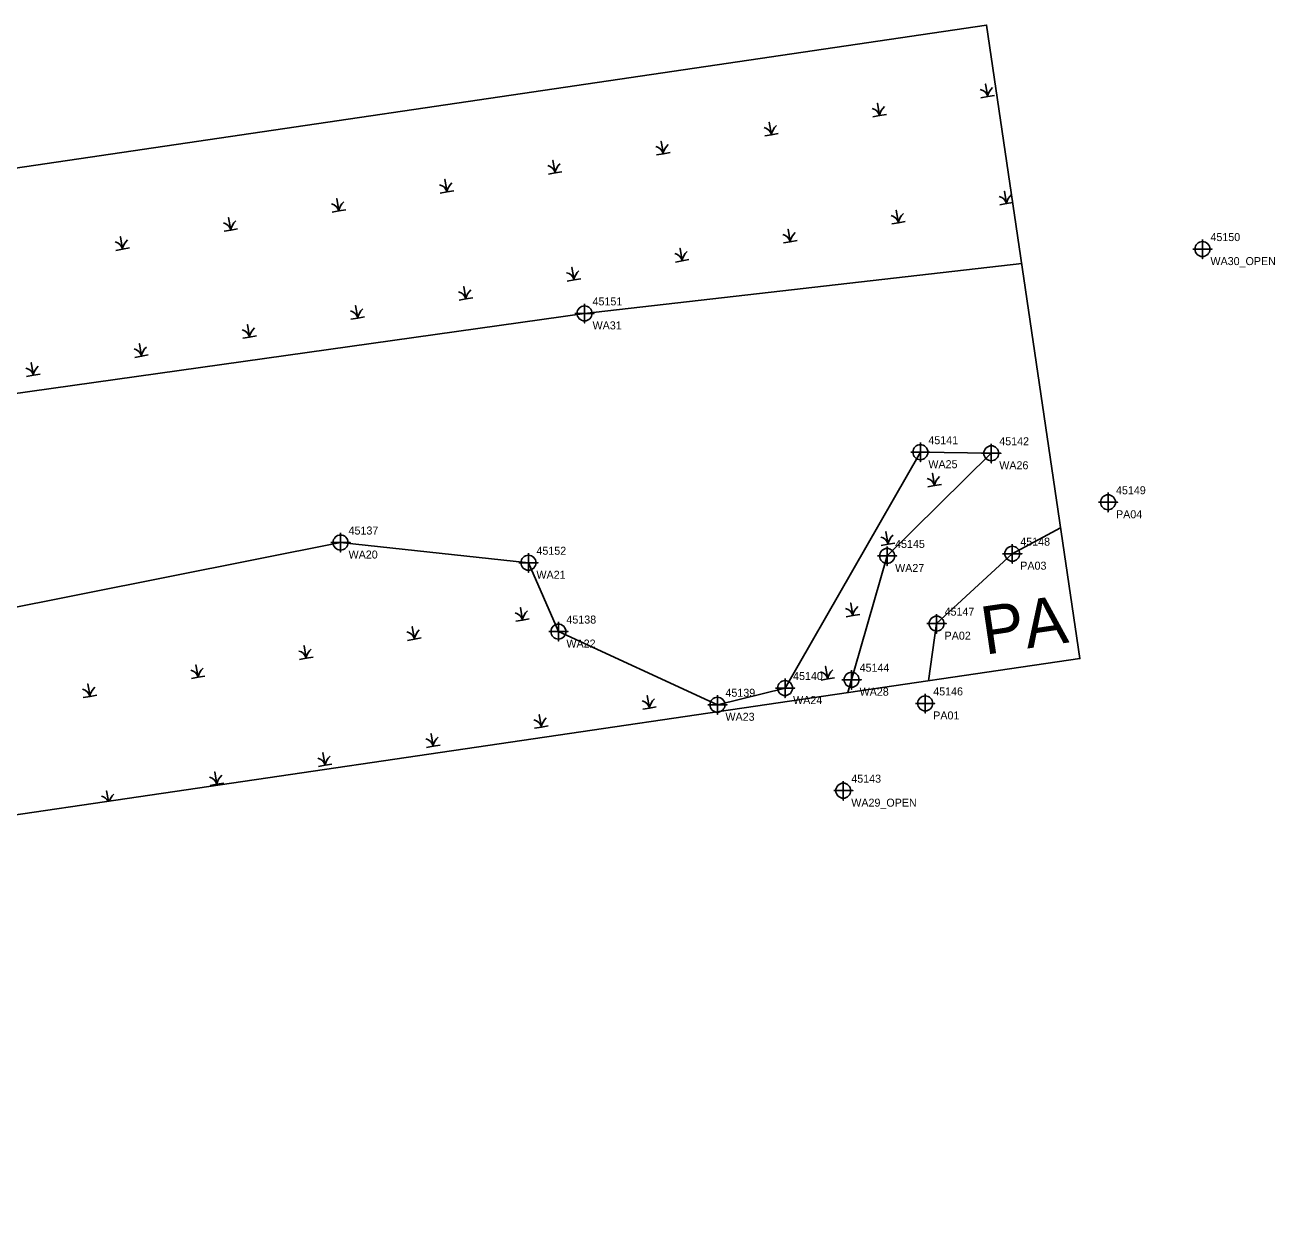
# Model space of a CAD drawing. Extents: x 2111078 to 2112659, y 581517 to 581899.
# Drawn here: x 2112268.6 to 2112659.1, y 581523.2 to 581899.2 of the extents above; entities that cross this region are included whole.
import ezdxf

# ---------------------------------------------------------------- set-up
doc = ezdxf.new("R2010")
doc.units = 0
for name, color, linetype in [('Default', 7, 'Continuous'), ('Exist Environmental Wetland Boundary', 7, 'Continuous'), ('Exist Environmental Wetland Boundary Cogo Comment', 7, 'Continuous'), ('Exist Environmental Wetland Boundary Cogo Number', 7, 'Continuous'), ('Exist Environmental Wetland Boundary Cogo Point CELL', 7, 'Continuous'), ('Exist Hydro Jurisdictional Stream or Body of Water Mitigable', 7, 'Continuous'), ('Exist Hydro Jurisdictional Stream or Body of Water Mitigable Cogo Comment', 7, 'Continuous'), ('Exist Hydro Jurisdictional Stream or Body of Water Mitigable Cogo Number', 7, 'Continuous'), ('Exist Hydro Jurisdictional Stream or Body of Water Mitigable Cogo Point CELL', 7, 'Continuous'), ('Exist Hydro Jurisdictional Stream or Body of Water Mitigable Text', 7, 'Continuous'), ('Exist Hydro Swamp or Marsh', 7, 'Continuous')]:
    doc.layers.add(name, color=color, linetype=linetype)

msp = doc.modelspace()

# ---------------------------------------------------------------- linework, layer by layer
at = {"layer": 'Default'}
msp.add_lwpolyline([(2111089.87, 581523.16), (2111077.52, 581722.78), (2111579.66, 581753.48), (2112568.99, 581899.18), (2112598.13, 581701.32), (2111600.4, 581554.74), (2111516.52, 581549.55)], close=True, dxfattribs=at)
at = {"layer": 'Exist Environmental Wetland Boundary'}
msp.add_lwpolyline([(2112579.95, 581824.73), (2112443.39, 581809.13), (2112256.64, 581782.86), (2112109, 581759.83), (2112096.72, 581743.78), (2112106.82, 581715.7), (2112118.04, 581694.33), (2112231.63, 581710.61), (2112367.17, 581737.55), (2112425.86, 581731.24), (2112435.22, 581709.75), (2112484.9, 581686.89), (2112506.03, 581692.11), (2112548.3, 581765.77), (2112570.44, 581765.42), (2112537.9, 581733.37), (2112525.65, 581690.67)], dxfattribs=at)
at = {"layer": 'Exist Environmental Wetland Boundary Cogo Point CELL'}
for points in [[(2112636.41, 581832.2), (2112636.41, 581826.2), (2112636.41, 581829.2), (2112639.41, 581829.2), (2112633.41, 581829.2)], [(2112443.39, 581812.12), (2112443.39, 581806.12), (2112443.39, 581809.12), (2112446.39, 581809.12), (2112440.39, 581809.12)], [(2112548.29, 581768.77), (2112548.29, 581762.77), (2112548.29, 581765.77), (2112551.29, 581765.77), (2112545.29, 581765.77)], [(2112570.44, 581768.42), (2112570.44, 581762.42), (2112570.44, 581765.42), (2112573.44, 581765.42), (2112567.44, 581765.42)], [(2112367.17, 581740.55), (2112367.17, 581734.55), (2112367.17, 581737.55), (2112370.17, 581737.55), (2112364.17, 581737.55)], [(2112537.9, 581736.36), (2112537.9, 581730.36), (2112537.9, 581733.36), (2112540.9, 581733.36), (2112534.9, 581733.36)], [(2112425.86, 581734.24), (2112425.86, 581728.24), (2112425.86, 581731.24), (2112428.86, 581731.24), (2112422.86, 581731.24)], [(2112435.22, 581712.75), (2112435.22, 581706.75), (2112435.22, 581709.75), (2112438.22, 581709.75), (2112432.22, 581709.75)], [(2112526.81, 581697.71), (2112526.81, 581691.71), (2112526.81, 581694.71), (2112529.81, 581694.71), (2112523.81, 581694.71)], [(2112506.03, 581695.11), (2112506.03, 581689.11), (2112506.03, 581692.11), (2112509.03, 581692.11), (2112503.03, 581692.11)], [(2112484.9, 581689.89), (2112484.9, 581683.89), (2112484.9, 581686.89), (2112487.9, 581686.89), (2112481.9, 581686.89)], [(2112524.21, 581663.06), (2112524.21, 581657.06), (2112524.21, 581660.06), (2112527.21, 581660.06), (2112521.21, 581660.06)]]:
    msp.add_lwpolyline(points, dxfattribs=at)
for centre in [(2112636.41, 581829.2), (2112443.39, 581809.12), (2112548.29, 581765.77), (2112570.44, 581765.42), (2112367.17, 581737.55), (2112537.9, 581733.36), (2112425.86, 581731.24), (2112435.22, 581709.75), (2112526.81, 581694.71), (2112506.03, 581692.11), (2112484.9, 581686.89), (2112524.21, 581660.06)]:
    msp.add_circle(centre, 2.34, dxfattribs=at)
at = {"layer": 'Exist Hydro Jurisdictional Stream or Body of Water Mitigable'}
msp.add_lwpolyline([(2112550.82, 581694.37), (2112553.36, 581712.22), (2112577, 581734.07), (2112592.11, 581742.18)], dxfattribs=at)
at = {"layer": 'Exist Hydro Jurisdictional Stream or Body of Water Mitigable Cogo Point CELL'}
for points in [[(2112606.91, 581753.13), (2112606.91, 581747.13), (2112606.91, 581750.13), (2112609.91, 581750.13), (2112603.91, 581750.13)], [(2112577, 581737.07), (2112577, 581731.07), (2112577, 581734.07), (2112580, 581734.07), (2112574, 581734.07)], [(2112553.36, 581715.22), (2112553.36, 581709.22), (2112553.36, 581712.22), (2112556.36, 581712.22), (2112550.36, 581712.22)], [(2112549.81, 581690.31), (2112549.81, 581684.31), (2112549.81, 581687.31), (2112552.81, 581687.31), (2112546.81, 581687.31)]]:
    msp.add_lwpolyline(points, dxfattribs=at)
for centre in [(2112606.91, 581750.13), (2112577, 581734.07), (2112553.36, 581712.22), (2112549.81, 581687.31)]:
    msp.add_circle(centre, 2.34, dxfattribs=at)
at = {"layer": 'Exist Hydro Swamp or Marsh'}
for p, q in [((2112552.43, 581757.08), (2112552.43, 581757.08)), ((2112537.9, 581738.78), (2112537.9, 581738.78)), ((2112526.92, 581716.49), (2112526.92, 581716.49)), ((2112519.08, 581696.72), (2112519.08, 581696.72))]:
    msp.add_line(p, q, dxfattribs=at)
for points in [[(2112567.22, 581876.46), (2112569.33, 581876.83), (2112568.65, 581880.72), (2112569.33, 581876.83), (2112571.45, 581877.21)], [(2112533.44, 581870.5), (2112535.56, 581870.88), (2112534.87, 581874.76), (2112535.56, 581870.88), (2112537.67, 581871.25)], [(2112499.66, 581864.55), (2112501.78, 581864.92), (2112501.09, 581868.81), (2112501.78, 581864.92), (2112503.89, 581865.29)], [(2112465.88, 581858.59), (2112468, 581858.96), (2112467.31, 581862.85), (2112468, 581858.96), (2112470.11, 581859.34)], [(2112432.1, 581852.64), (2112434.22, 581853.01), (2112433.53, 581856.89), (2112434.22, 581853.01), (2112436.33, 581853.38)], [(2112398.32, 581846.68), (2112400.44, 581847.05), (2112399.75, 581850.94), (2112400.44, 581847.05), (2112402.55, 581847.43)], [(2112364.54, 581840.72), (2112366.66, 581841.1), (2112365.97, 581844.98), (2112366.66, 581841.1), (2112368.77, 581841.47)], [(2112573.11, 581843.03), (2112575.23, 581843.4), (2112574.54, 581847.29), (2112575.23, 581843.4), (2112577.15, 581843.74)], [(2112539.33, 581837.07), (2112541.45, 581837.45), (2112540.76, 581841.33), (2112541.45, 581837.45), (2112543.57, 581837.82)], [(2112330.76, 581834.77), (2112332.88, 581835.14), (2112332.19, 581839.03), (2112332.88, 581835.14), (2112334.99, 581835.51)], [(2112296.98, 581828.81), (2112299.1, 581829.18), (2112298.41, 581833.07), (2112299.1, 581829.18), (2112301.21, 581829.56)], [(2112505.55, 581831.12), (2112507.67, 581831.49), (2112506.98, 581835.38), (2112507.67, 581831.49), (2112509.79, 581831.87)], [(2112471.77, 581825.16), (2112473.89, 581825.54), (2112473.21, 581829.42), (2112473.89, 581825.54), (2112476.01, 581825.91)], [(2112437.99, 581819.21), (2112440.11, 581819.58), (2112439.43, 581823.46), (2112440.11, 581819.58), (2112442.23, 581819.95)], [(2112404.21, 581813.25), (2112406.33, 581813.62), (2112405.65, 581817.51), (2112406.33, 581813.62), (2112408.45, 581814)], [(2112370.43, 581807.29), (2112372.55, 581807.67), (2112371.87, 581811.55), (2112372.55, 581807.67), (2112374.67, 581808.04)], [(2112336.65, 581801.34), (2112338.77, 581801.71), (2112338.09, 581805.6), (2112338.77, 581801.71), (2112340.89, 581802.08)], [(2112302.87, 581795.38), (2112304.99, 581795.75), (2112304.31, 581799.64), (2112304.99, 581795.75), (2112307.11, 581796.13)], [(2112269.09, 581789.42), (2112271.21, 581789.8), (2112270.53, 581793.68), (2112271.21, 581789.8), (2112273.33, 581790.17)], [(2112550.62, 581754.95), (2112552.74, 581755.32), (2112552.05, 581759.21), (2112552.74, 581755.32), (2112554.85, 581755.7)], [(2112536.09, 581736.65), (2112538.21, 581737.03), (2112537.53, 581740.91), (2112538.21, 581737.03), (2112540.33, 581737.4)], [(2112421.9, 581712.96), (2112424.01, 581713.33), (2112423.33, 581717.22), (2112424.01, 581713.33), (2112426.13, 581713.71)], [(2112525.11, 581714.37), (2112527.23, 581714.74), (2112526.55, 581718.62), (2112527.23, 581714.74), (2112529.35, 581715.11)], [(2112388.12, 581707), (2112390.23, 581707.38), (2112389.55, 581711.26), (2112390.23, 581707.38), (2112392.35, 581707.75)], [(2112354.34, 581701.05), (2112356.45, 581701.42), (2112355.77, 581705.31), (2112356.45, 581701.42), (2112358.57, 581701.8)], [(2112320.56, 581695.09), (2112322.68, 581695.47), (2112321.99, 581699.35), (2112322.68, 581695.47), (2112324.79, 581695.84)], [(2112517.27, 581694.59), (2112519.39, 581694.96), (2112518.7, 581698.85), (2112519.39, 581694.96), (2112521.5, 581695.34)], [(2112286.78, 581689.14), (2112288.9, 581689.51), (2112288.21, 581693.39), (2112288.9, 581689.51), (2112291.01, 581689.88)], [(2112461.57, 581685.49), (2112463.69, 581685.86), (2112463, 581689.75), (2112463.69, 581685.86), (2112465.81, 581686.23)], [(2112427.79, 581679.53), (2112429.91, 581679.91), (2112429.22, 581683.79), (2112429.91, 581679.91), (2112432.03, 581680.28)], [(2112394.01, 581673.58), (2112396.13, 581673.95), (2112395.44, 581677.83), (2112396.13, 581673.95), (2112398.25, 581674.32)], [(2112360.23, 581667.62), (2112362.35, 581667.99), (2112361.66, 581671.88), (2112362.35, 581667.99), (2112364.47, 581668.37)], [(2112326.45, 581661.66), (2112328.57, 581662.04), (2112327.88, 581665.92), (2112328.57, 581662.04), (2112330.69, 581662.41)], [(2112294.67, 581656.74), (2112294.1, 581659.97), (2112294.67, 581656.74)]]:
    msp.add_lwpolyline(points, dxfattribs=at)
for centre, radius, start, end in [((2112566.35, 581876.08), 3.07, 14.1403, 77.535), ((2112574.09, 581876.13), 4.81, 132.1274, 171.6222), ((2112532.57, 581870.13), 3.07, 14.1403, 77.535), ((2112540.31, 581870.18), 4.81, 132.1274, 171.6222), ((2112506.53, 581864.22), 4.81, 132.1274, 171.6222), ((2112498.79, 581864.17), 3.07, 14.1403, 77.535), ((2112465.01, 581858.21), 3.07, 14.1403, 77.535), ((2112472.75, 581858.26), 4.81, 132.1274, 171.6222), ((2112438.97, 581852.31), 4.81, 132.1274, 171.6222), ((2112431.23, 581852.26), 3.07, 14.1403, 77.535), ((2112397.45, 581846.3), 3.07, 14.1403, 77.535), ((2112405.19, 581846.35), 4.81, 132.1274, 171.6222), ((2112371.41, 581840.4), 4.81, 132.1274, 171.6222), ((2112572.25, 581842.65), 3.07, 14.1403, 77.535), ((2112579.98, 581842.7), 4.81, 132.1274, 171.6222), ((2112363.68, 581840.34), 3.07, 14.1403, 77.535), ((2112546.2, 581836.75), 4.81, 132.1274, 171.6222), ((2112329.9, 581834.39), 3.07, 14.1403, 77.535), ((2112337.63, 581834.44), 4.81, 132.1274, 171.6222), ((2112538.47, 581836.7), 3.07, 14.1403, 77.535), ((2112303.85, 581828.48), 4.81, 132.1274, 171.6222), ((2112504.69, 581830.74), 3.07, 14.1403, 77.535), ((2112512.42, 581830.79), 4.81, 132.1274, 171.6222), ((2112296.12, 581828.43), 3.07, 14.1403, 77.535), ((2112478.64, 581824.84), 4.81, 132.1274, 171.6222), ((2112470.91, 581824.78), 3.07, 14.1403, 77.535), ((2112437.13, 581818.83), 3.07, 14.1403, 77.535), ((2112444.86, 581818.88), 4.81, 132.1274, 171.6222), ((2112411.09, 581812.92), 4.81, 132.1274, 171.6222), ((2112403.35, 581812.87), 3.07, 14.1403, 77.535), ((2112369.57, 581806.92), 3.07, 14.1403, 77.535), ((2112377.31, 581806.97), 4.81, 132.1274, 171.6222), ((2112335.79, 581800.96), 3.07, 14.1403, 77.535), ((2112343.53, 581801.01), 4.81, 132.1274, 171.6222), ((2112302.01, 581795), 3.07, 14.1403, 77.535), ((2112309.75, 581795.05), 4.81, 132.1274, 171.6222), ((2112268.23, 581789.05), 3.07, 14.1403, 77.535), ((2112275.97, 581789.1), 4.81, 132.1274, 171.6222), ((2112557.49, 581754.62), 4.81, 132.1274, 171.6222), ((2112549.75, 581754.57), 3.07, 14.1403, 77.535), ((2112535.23, 581736.28), 3.07, 14.1403, 77.535), ((2112542.97, 581736.33), 4.81, 132.1274, 171.6222), ((2112421.03, 581712.58), 3.07, 14.1403, 77.535), ((2112428.77, 581712.63), 4.81, 132.1274, 171.6222), ((2112524.25, 581713.99), 3.07, 14.1403, 77.535), ((2112531.98, 581714.04), 4.81, 132.1274, 171.6222), ((2112387.25, 581706.63), 3.07, 14.1403, 77.535), ((2112394.99, 581706.68), 4.81, 132.1274, 171.6222), ((2112353.47, 581700.67), 3.07, 14.1403, 77.535), ((2112361.21, 581700.72), 4.81, 132.1274, 171.6222), ((2112319.69, 581694.71), 3.07, 14.1403, 77.535), ((2112327.43, 581694.77), 4.81, 132.1274, 171.6222), ((2112516.4, 581694.21), 3.07, 14.1403, 77.535), ((2112524.14, 581694.26), 4.81, 132.1274, 171.6222), ((2112285.91, 581688.76), 3.07, 14.1403, 77.535), ((2112293.65, 581688.81), 4.81, 132.1274, 171.6222), ((2112460.71, 581685.11), 3.07, 14.1403, 77.535), ((2112468.44, 581685.16), 4.81, 132.1274, 171.6222), ((2112426.93, 581679.15), 3.07, 14.1403, 77.535), ((2112434.66, 581679.21), 4.81, 132.1274, 171.6222), ((2112393.15, 581673.2), 3.07, 14.1403, 77.535), ((2112400.88, 581673.25), 4.81, 132.1274, 171.6222), ((2112359.37, 581667.24), 3.07, 14.1403, 77.535), ((2112367.1, 581667.29), 4.81, 132.1274, 171.6222), ((2112325.59, 581661.29), 3.07, 14.1403, 77.535), ((2112333.32, 581661.34), 4.81, 132.1274, 171.6222), ((2112291.81, 581655.33), 3.07, 26.8826, 77.535), ((2112299.54, 581655.38), 4.81, 132.1274, 163.0953)]:
    msp.add_arc(centre, radius, start, end, dxfattribs=at)

# ---------------------------------------------------------------- texts
at = {"layer": 'Exist Environmental Wetland Boundary Cogo Comment'}
for s, p in [('WA30_OPEN', (2112638.91, 581824.2)), ('WA31', (2112445.89, 581804.12)), ('WA25', (2112550.79, 581760.77)), ('WA26', (2112572.94, 581760.43)), ('WA20', (2112369.67, 581732.55)), ('WA27', (2112540.4, 581728.36)), ('WA21', (2112428.36, 581726.24)), ('WA22', (2112437.72, 581704.75)), ('WA28', (2112529.31, 581689.71)), ('WA24', (2112508.53, 581687.11)), ('WA23', (2112487.4, 581681.89)), ('WA29_OPEN', (2112526.71, 581655.06))]:
    msp.add_text(s, height=2.5, dxfattribs=at).set_placement(p)
at = {"layer": 'Exist Environmental Wetland Boundary Cogo Number'}
for s, p in [('45150', (2112638.91, 581831.7)), ('45151', (2112445.89, 581811.62)), ('45141', (2112550.79, 581768.27)), ('45142', (2112572.94, 581767.93)), ('45137', (2112369.67, 581740.05)), ('45145', (2112540.4, 581735.86)), ('45152', (2112428.36, 581733.74)), ('45138', (2112437.72, 581712.25)), ('45144', (2112529.31, 581697.21)), ('45140', (2112508.53, 581694.61)), ('45139', (2112487.4, 581689.39)), ('45143', (2112526.71, 581662.56))]:
    msp.add_text(s, height=2.5, dxfattribs=at).set_placement(p)
at = {"layer": 'Exist Hydro Jurisdictional Stream or Body of Water Mitigable Cogo Comment'}
for s, p in [('PA04', (2112609.41, 581745.13)), ('PA03', (2112579.5, 581729.07)), ('PA02', (2112555.86, 581707.22)), ('PA01', (2112552.31, 581682.31))]:
    msp.add_text(s, height=2.5, dxfattribs=at).set_placement(p)
at = {"layer": 'Exist Hydro Jurisdictional Stream or Body of Water Mitigable Cogo Number'}
for s, p in [('45149', (2112609.41, 581752.63)), ('45148', (2112579.5, 581736.57)), ('45147', (2112555.86, 581714.72)), ('45146', (2112552.31, 581689.81))]:
    msp.add_text(s, height=2.5, dxfattribs=at).set_placement(p)
at = {"layer": 'Exist Hydro Jurisdictional Stream or Body of Water Mitigable Text'}
msp.add_text('PA', height=15, rotation=8.3579, dxfattribs=at).set_placement((2112568.47, 581702.49))

doc.saveas('drawing.dxf')
